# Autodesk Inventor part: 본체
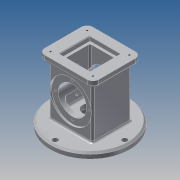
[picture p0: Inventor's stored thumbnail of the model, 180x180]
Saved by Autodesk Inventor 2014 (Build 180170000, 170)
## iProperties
Created: 2019-08
Part Number: 본체
Material: 알루미늄 6061
Document SubType Name: Modeling
Designer: kb542-14
Density: 2.71 g/cm^3
Appearance: 알루미늄 - 평지
Mass: 1040.33 g
Surface Area: 788.05 cm^2
Volume: 383.884 cm^3
Author: kb542-14
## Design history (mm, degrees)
sketch "스케치1"
  geometry: L1 (37, 33)-(-37, 33); L2 (-37, 33)-(-37, -33); L3 (-37, -33)-(37, -33); L4 (37, -33)-(37, 33); L5 (37, 33)-(-37, -33); L6 (-37, 33)-(37, -33); 1 further point
  constraints: 12 end point, 2 midpoint, 2 parallel, 1 horizontal, 1 perpendicular
  dimensions: "d1" = 74 distance of L1.start L1.end; "d2" = 66 distance of L1.end L2.end
extrude "돌출1" new body sketch "스케치1" distance "d3" = 88; taper "d4" = 0 deg
sketch "스케치2"
  geometry: L1 (46, 41)-(-46, 41); L2 (-46, 41)-(-46, -41); L3 (-46, -41)-(46, -41); L4 (46, -41)-(46, 41); L5 (46, 41)-(-46, -41); L6 (-46, 41)-(46, -41); 1 further point
  constraints: 12 end point, 2 midpoint, 2 parallel, 1 horizontal, 1 perpendicular
  dimensions: "d5" = 92 distance of L1.start L1.end; "d6" = 82 distance of L1.end L2.end
extrude "돌출2" join sketch "스케치2" distance "d7" = 10; taper "d8" = 0 deg
sketch "스케치3"
  geometry: C1 r 67.5 at (0, 0); 1 further point
  constraints: 1 centre point, 1 coincident
  dimensions: "d9" = 135 diameter of C1
extrude "돌출3" join sketch "스케치3" distance "d10" = 10; taper "d11" = 0 deg
sketch "스케치5"
  geometry: L1 (-33, 88)-(-41, 88) reference; L2 (-41, 88)-(-41, 98) reference; L3 (-41, 98)-(41, 98) reference; L4 (41, 98)-(41, 88) reference; L5 (41, 88)-(33, 88) reference; L6 (33, 88)-(33, 0) reference; L7 (33, 0)-(67.5, 0) reference; L8 (67.5, 0)-(67.5, -10) reference; L9 (67.5, -10)-(-67.5, -10) reference; L10 (-67.5, -10)-(-67.5, 0) reference; L11 (-67.5, 0)-(-33, 0) reference; L12 (-33, 0)-(-33, 88) reference; L13 (-33, 44)-(33, 44); L14 (-33, 79)-(-30, 79); L15 (-30, 79)-(-30, 68); L16 (-30, 68)-(30, 68); L17 (30, 68)-(30, 79); L18 (30, 79)-(33, 79); L19 (-33, 79)-(-33, 44); L20 (33, 79)-(33, 44); 1 further point
  constraints: 16 end point, 4 parallel, 2 collinear, 2 midpoint, 2 point on line, 1 perpendicular
  dimensions: "d18" = 70 diameter of L14 L13; "d20" = 48 diameter of L16 L13; "d21" = 70 diameter of L18 L13; "d22" = 3 distance of L14.start L14.end; "d23" = 3 distance of L17.end L18.end
revolve "회전2" sketch "스케치5" stored, may be unused: angle "d24" = 90 deg
sketch "스케치6"
  geometry: L1 (26, 26)-(-26, 26); L2 (-26, 26)-(-26, -26); L3 (-26, -26)-(26, -26); L4 (26, -26)-(26, 26); L5 (26, 26)-(-26, -26); L6 (-26, 26)-(26, -26); 1 further point
  constraints: 12 end point, 2 midpoint, 2 parallel, 1 horizontal, 1 perpendicular
  dimensions: "d25" = 52 distance of L1.end L2.end; "d26" = 52 distance of L1.start L1.end
extrude "돌출4" cut sketch "스케치6" distance "d27" = 8; taper "d28" = 0 deg
sketch "스케치7"
  geometry: L1 (22, 22)-(-22, 22); L2 (-22, 22)-(-22, -22); L3 (-22, -22)-(22, -22); L4 (22, -22)-(22, 22); L5 (22, 22)-(-22, -22); L6 (-22, 22)-(22, -22); 1 further point
  constraints: 12 end point, 2 midpoint, 2 parallel, 1 horizontal, 1 perpendicular
  dimensions: "d29" = 44 distance of L1.end L2.end; "d30" = 44 distance of L1.start L1.end
extrude "돌출5" cut sketch "스케치7" distance "d31" = 74; taper "d32" = 0 deg
sketch "스케치8"
  geometry: C1 r 67.5 at (0, 0) reference; C2 r 25 at (0, 0); C3 r 12.5 at (0, 0)
  constraints: 2 centre point, 2 coincident
  dimensions: "d34" = 50 diameter of C2; "d35" = 25 diameter of C3
extrude "돌출6" cut sketch "스케치8" distance "d36" = 50; taper "d37" = 0 deg
extrude "돌출7" cut sketch "스케치8" distance "d38" = 18; taper "d39" = 0 deg
sketch "스케치9"
  geometry: L1 (-88, 66)-(-88, 0) reference; L2 (-98, 100.5)-(-98, -34.5) reference; 5 further points
  constraints: 2 horizontal alignment, 2 midpoint
  dimensions: "d40" = 37 distance from line of L2 point (-61, 33); "d41" = 43 distance of point (-61, 33) point (-18, 33)
hole "구멍1" sketch "스케치9" at (-18, 33), (-61, 33) diameter "d42" = 4.917; stored, may be unused: countersink angle "d46" = 90 deg, drill point angle "d48" = 118 deg; dims "d43" = 6, "d44" = 4, "d45" = 2, "d47" = 22.75
fillet "모깎기1" dims "d49" = 3
fillet "모깎기2" dims "d50" = 3
fillet "모깎기3" dims "d51" = 3
fillet "모깎기4" dims "d52" = 10
fillet "모깎기6" dims "d54" = 3
fillet "모깎기7" dims "d55" = 3
fillet "모깎기8" dims "d56" = 3
chamfer "모따기1" distance "d57" = 3; stored, may be unused: second distance "d58" = 2, angle "d59" = 45 deg
fillet "모깎기9" dims "d60" = 3
sketch "스케치12"
  geometry: C1 r 64.5 at (0, 0) reference; C2 r 4.5 at (0, 59); C3 r 4.5 at (0, -59); C4 r 4.5 at (59, 0); A1 r 59 centre (0, 0) between (0, 59) and (0, -59)
  constraints: 4 centre point, 3 point on circle, 2 vertical alignment, 1 coincident, 1 horizontal alignment
  dimensions: "d61" = 118 diameter of A1; "d62" = 9 diameter of C2; "d63" = 9 diameter of C4; "d65" = 9 diameter of C3
extrude "돌출8" cut sketch "스케치12" stored distance "d66" = 18; taper "d67" = 0 deg
sketch "스케치13"
  geometry: A1 r 10 centre (36, -31) between (36, -41) and (46, -31) reference; A2 r 10 centre (36, 31) between (46, 31) and (36, 41) reference; A3 r 10 centre (-36, 31) between (-36, 41) and (-46, 31) reference; A4 r 10 centre (-36, -31) between (-46, -31) and (-36, -41) reference; 5 further points
  constraints: 4 coincident
hole "구멍2" sketch "스케치13" at (-36, 31), (-36, -31), (36, -31), (36, 31) diameter "d68" = 3.242; stored, may be unused: countersink angle "d72" = 90 deg, drill point angle "d74" = 118 deg; dims "d69" = 4, "d70" = 4, "d71" = 2, "d73" = 6
sketch "스케치14" dims "d75" = 58
  geometry: C1 r 24 at (0, 0) reference; C2 r 35 at (0, 0) reference; 3 further points
  constraints: 2 vertical alignment, 1 coincident, 2 other
hole "구멍3" sketch "스케치14" at (0, -29) diameter "d76" = 3.242; stored, may be unused: countersink angle "d80" = 90 deg, drill point angle "d82" = 118 deg; dims "d77" = 4, "d78" = 4, "d79" = 2, "d81" = 6
sketch "스케치15"
  geometry: L1 (-34, -36)-(34, -36) reference; L2 (-40, 30)-(-40, -30) reference; L3 (34, 36)-(-34, 36) reference; L4 (40, -30)-(40, 30) reference; C1 r 4.5 at (0, -59) reference; C2 r 4.5 at (0, 59) reference; C3 r 4.5 at (59, 0) reference; C4 r 64.5 at (0, 0) reference; A1 r 6 centre (34, -30) between (34, -36) and (40, -30) reference; A2 r 6 centre (-34, -30) between (-40, -30) and (-34, -36) reference; A3 r 6 centre (-34, 30) between (-34, 36) and (-40, 30) reference; A4 r 6 centre (34, 30) between (40, 30) and (34, 36) reference; 1 further point
  constraints: 1 other
chamfer "모따기2" distance "d86" = 1; stored, may be unused: second distance "d87" = 2, angle "d88" = 45 deg
fillet "모깎기10" dims "d89" = 3
node "솔리드1"
pattern_circular "원형 패턴1" dims angle "d84" = 360 deg
mirror "대칭1"
node "절단 모서리 투영2"
